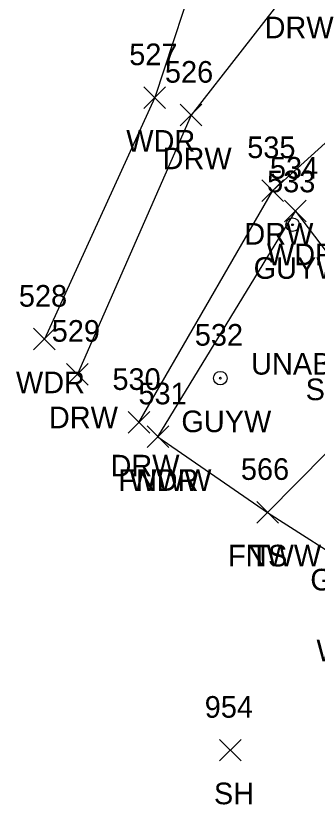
# Model space of a CAD drawing. Extents: x 1764889 to 1767296, y 695936 to 698960.
# Drawn here: x 1766254.4 to 1766282.3, y 696566.7 to 696640.9 of the extents above; entities that cross this region are included whole.
import ezdxf

# ---------------------------------------------------------------- set-up
doc = ezdxf.new("R2010")
doc.units = 0
for name, color, linetype in [('D_C', 7, 'Continuous'), ('L_A', 7, 'Continuous'), ('L_I', 7, 'Continuous'), ('L_TIC', 7, 'Continuous'), ('LAWA', 7, 'Continuous'), ('LELB', 7, 'Continuous'), ('LFNC', 7, 'Continuous'), ('R_A', 7, 'Continuous'), ('R_I', 7, 'Continuous'), ('R_TIC', 7, 'Continuous'), ('RDW', 7, 'Continuous'), ('S_C', 7, 'Continuous'), ('U_A', 7, 'Continuous'), ('U_I', 7, 'Continuous'), ('UPGW', 7, 'Continuous')]:
    doc.layers.add(name, color=color, linetype=linetype)

msp = doc.modelspace()

# ---------------------------------------------------------------- linework, layer by layer
at = {"layer": 'L_TIC'}
for points in [[(1766266.217, 696632.394), (1766268.217, 696634.394)], [(1766268.217, 696632.394), (1766266.217, 696634.394)], [(1766279.23, 696621.903), (1766281.23, 696623.903)], [(1766281.23, 696621.903), (1766279.23, 696623.903)], [(1766256.01, 696610.066), (1766258.01, 696612.066)], [(1766258.01, 696610.066), (1766256.01, 696612.066)], [(1766266.506, 696601.037), (1766268.506, 696603.037)], [(1766268.506, 696601.037), (1766266.506, 696603.037)], [(1766266.506, 696601.037), (1766268.506, 696603.037)], [(1766268.506, 696601.037), (1766266.506, 696603.037)], [(1766276.65, 696594.052), (1766278.65, 696596.052)], [(1766278.65, 696594.052), (1766276.65, 696596.052)], [(1766276.65, 696594.052), (1766278.65, 696596.052)], [(1766278.65, 696594.052), (1766276.65, 696596.052)], [(1766273.201, 696572.063), (1766275.201, 696574.063)], [(1766275.201, 696572.063), (1766273.201, 696574.063)]]:
    msp.add_lwpolyline(points, dxfattribs=at)
at = {"layer": 'LAWA'}
for points in [[(1766258.627, 696662.256), (1766271.573, 696646.629), (1766267.217, 696633.394), (1766257.01, 696611.066)], [(1766267.506, 696602.037), (1766280.23, 696622.903), (1766290.113, 696609.911), (1766295.555, 696605.374), (1766300.13, 696593.204), (1766307.624, 696581.45)]]:
    msp.add_lwpolyline(points, dxfattribs=at)
at = {"layer": 'LELB'}
msp.add_lwpolyline([(1766288.604, 696606.107), (1766277.65, 696595.052)], dxfattribs=at)
at = {"layer": 'LFNC'}
msp.add_lwpolyline([(1766267.506, 696602.037), (1766277.65, 696595.052), (1766286.237, 696589.556), (1766303.059, 696578.689), (1766299.857, 696566.706)], dxfattribs=at)
at = {"layer": 'R_TIC'}
for points in [[(1766269.575, 696630.775), (1766271.575, 696632.775)], [(1766271.575, 696630.775), (1766269.575, 696632.775)], [(1766277.134, 696623.8), (1766279.134, 696625.8)], [(1766279.134, 696623.8), (1766277.134, 696625.8)], [(1766259.054, 696606.824), (1766261.054, 696608.824)], [(1766261.054, 696606.824), (1766259.054, 696608.824)], [(1766264.751, 696602.369), (1766266.751, 696604.369)], [(1766266.751, 696602.369), (1766264.751, 696604.369)]]:
    msp.add_lwpolyline(points, dxfattribs=at)
at = {"layer": 'RDW'}
for points in [[(1766289.173, 696652.924), (1766284.86, 696649.837), (1766280.005, 696643.877), (1766270.575, 696631.775), (1766260.054, 696607.824)], [(1766265.751, 696603.369), (1766278.134, 696624.8), (1766287.808, 696633.57), (1766291.511, 696636.823), (1766296.509, 696639.295)]]:
    msp.add_lwpolyline(points, dxfattribs=at)
at = {"layer": 'UPGW'}
for centre, radius in [((1766279.969, 696621.642), 0.625), ((1766279.969, 696621.642), 0.0833), ((1766273.284, 696607.462), 0.625), ((1766273.284, 696607.462), 0.0833)]:
    msp.add_circle(centre, radius, dxfattribs=at)

# ---------------------------------------------------------------- texts
at = {"layer": 'D_C'}
msp.add_text('UNABLE TO LOCATE PIPES', height=2, dxfattribs=at).set_placement((1766276.129, 696607.785))
at = {"layer": 'L_A'}
for s, p in [('WDR', (1766264.58, 696628.394)), ('WDR', (1766277.592, 696617.903)), ('WDR', (1766254.373, 696606.066)), ('FNWW', (1766263.853, 696597.037)), ('WDR', (1766264.868, 696597.037)), ('FNWW', (1766273.996, 696590.052)), ('TS', (1766276.059, 696590.052)), ('SH', (1766272.689, 696568.063))]:
    msp.add_text(s, height=2, dxfattribs=at).set_placement(p)
at = {"layer": 'L_I'}
for s, p in [('527', (1766264.855, 696636.394)), ('534', (1766277.868, 696625.903)), ('528', (1766254.648, 696614.066)), ('531', (1766265.711, 696605.037)), ('531', (1766265.711, 696605.037)), ('566', (1766275.185, 696598.052)), ('566', (1766275.185, 696598.052)), ('954', (1766271.839, 696576.063))]:
    msp.add_text(s, height=2, dxfattribs=at).set_placement(p)
at = {"layer": 'R_A'}
for p in [(1766277.375, 696638.877), (1766267.945, 696626.775), (1766275.504, 696619.8), (1766257.424, 696602.824), (1766263.121, 696598.369)]:
    msp.add_text('DRW', height=2, dxfattribs=at).set_placement(p)
at = {"layer": 'R_I'}
for s, p in [('526', (1766268.157, 696634.775)), ('535', (1766275.772, 696627.8)), ('529', (1766257.684, 696610.824)), ('530', (1766263.302, 696606.369))]:
    msp.add_text(s, height=2, dxfattribs=at).set_placement(p)
at = {"layer": 'S_C'}
msp.add_text('WARNING UNDERGROUND TEL CABLE', height=2, dxfattribs=at).set_placement((1766282.177, 696581.281))
at = {"layer": 'U_A'}
for s, p in [('GUYW', (1766276.363, 696616.642)), ('SUBT', (1766281.173, 696605.422)), ('GUYW', (1766269.678, 696602.462)), ('GUYW', (1766281.607, 696587.832))]:
    msp.add_text(s, height=2, dxfattribs=at).set_placement(p)
at = {"layer": 'U_I'}
for s, p in [('533', (1766277.607, 696624.642)), ('532', (1766270.922, 696610.462))]:
    msp.add_text(s, height=2, dxfattribs=at).set_placement(p)

doc.saveas('drawing.dxf')
